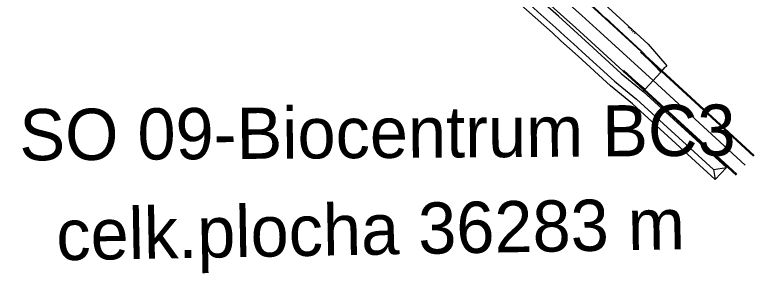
# Model space of a CAD drawing. Extents: x -551750 to -547457, y -1150683 to -1148508.
# Drawn here: x -550691.9 to -550511.6, y -1149048.8 to -1148985.7 of the extents above; entities that cross this region are included whole.
import ezdxf

# ---------------------------------------------------------------- set-up
doc = ezdxf.new("R2010")
doc.units = 0
doc.layers.add('u_popis_5000', color=7, linetype='Continuous')
doc.layers.add('u_trat navrh', color=7, linetype='Continuous')

msp = doc.modelspace()

# ---------------------------------------------------------------- linework, layer by layer
at = {"layer": 'u_trat navrh'}
for p, q in [((-550537.46, -1148992.84), (-550545.24, -1148985.69)), ((-550546.83, -1148987.42), (-550539.07, -1148994.56)), ((-550542.09, -1148988.59), (-550542.36, -1148988.89)), ((-550541.85, -1148989.08), (-550541.99, -1148989.22)), ((-550541.35, -1148989.27), (-550541.62, -1148989.56)), ((-550541.12, -1148989.75), (-550541.25, -1148989.9)), ((-550540.61, -1148989.94), (-550540.89, -1148990.24)), ((-550544.06, -1149000.02), (-550551.84, -1148992.87)), ((-550551.33, -1148992.32), (-550543.57, -1148999.45)), ((-550537.46, -1148992.84), (-550532.94, -1148998.14)), ((-550545.69, -1149001.92), (-550553.53, -1148994.71)), ((-550511.76, -1149020.19), (-550539.34, -1148994.85)), ((-550511.59, -1149020.01), (-550539.17, -1148994.67)), ((-550539.07, -1148994.56), (-550534.27, -1148999.59)), ((-550534.27, -1148999.59), (-550533.28, -1148998.51)), ((-550533.21, -1148998.43), (-550532.94, -1148998.14)), ((-550544.06, -1149000.02), (-550538.65, -1149004.37)), ((-550543.57, -1148999.45), (-550543.4, -1148999.27)), ((-550543.57, -1148999.45), (-550538.15, -1149003.81)), ((-550515.99, -1149024.79), (-550543.57, -1148999.45)), ((-550515.82, -1149024.61), (-550543.4, -1148999.27)), ((-550538.15, -1149003.81), (-550534.38, -1148999.7)), ((-550534.38, -1148999.7), (-550534.27, -1148999.59)), ((-550545.69, -1149001.92), (-550540.28, -1149006.26)), ((-550513.79, -1149022.4), (-550536.26, -1149001.75)), ((-550538.66, -1149004.36), (-550538.15, -1149003.81)), ((-550538.65, -1149004.37), (-550518.39, -1149022.98)), ((-550521.56, -1149023.46), (-550540.28, -1149006.26)), ((-550521.56, -1149023.46), (-550518.39, -1149022.98)), ((-550521.56, -1149023.46), (-550521.1, -1149025.92)), ((-550518.39, -1149022.98), (-550521.1, -1149025.92))]:
    msp.add_line(p, q, dxfattribs=at)
for points in [[(-550534.38, -1148999.7), (-550539.17, -1148994.67), (-550546.94, -1148987.53)], [(-550536.26, -1149001.75), (-550549.13, -1148989.92)], [(-550521.1, -1149025.92), (-550541.25, -1149007.4), (-550546.66, -1149003.06), (-550554.55, -1148995.81)]]:
    msp.add_lwpolyline(points, dxfattribs=at)
for radius, end in [(750, 76.89047), (746.75, 72.23343), (746, 72.23343), (743.5, 61.74591), (742, 61.3606), (755.75, 49.00677), (753.25, 48.92305), (753.4, 48.92305)]:
    msp.add_arc((-551056.59, -1149542.18), radius, 47.42068, end, dxfattribs=at)

# ---------------------------------------------------------------- texts
at = {"layer": 'u_popis_5000'}
for s, rotation, p in [('SO 09-Biocentrum BC3', 0.386, (-550690.76, -1149021.23)), ('celk.plocha 36283 m ', 1.0148, (-550681.7, -1149045.61))]:
    msp.add_text(s, height=12.5, rotation=rotation, dxfattribs=at).set_placement(p)

doc.saveas('drawing.dxf')
